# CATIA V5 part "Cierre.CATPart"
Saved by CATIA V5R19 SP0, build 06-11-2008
Part number: Cierre
Material "Plastic": density 1200 kg/m3, Young's modulus 2.2e+09 Pa, Poisson ratio 0.38, thermal expansion 6.84e-05 1/K
Bounding box of the stored display mesh (mm): x -7.75 to 7.75, y -18 to 0, z -6 to 6
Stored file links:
  C:\Users\José Miguel\Documents\Aprendizaxe Catia\Ejercicios_El gran libro de Catia\lote1\73_v5r19\Cierre.CATPart
  D:\TR\libro\ejemplo\terminados\COMPAS\compas.CATProduct
  D:\TR\libro\ejemplo\terminados\COMPAS\MANGO.CATPart
  C:\Users\José Miguel\Documents\Aprendizaxe Catia\Ejercicios_El gran libro de Catia\lote1\73_v5r19\Empunadura.CATPart
  D:\F&IC\ADMIN\MARKETING\logo\catia\CATIA5.es\Sello.CATPart
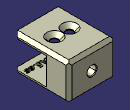
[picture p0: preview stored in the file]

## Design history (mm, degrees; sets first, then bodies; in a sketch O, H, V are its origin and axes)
Body1 "PartBody" (main body)
  Sketch1 on xy-plane, origin (0, 0, 0), H (1, 0, 0), V (0, 1, 0)
    point P1 (-7.75, 0)
    line L1 (-7.75, 0) -> (7.75, 0)
    line L2 (7.75, 0) -> (7.75, -18)
    line L3 (7.75, -18) -> (-7.75, -18)
    line L4 (-7.75, -18) -> (-7.75, 0)
    length L1 = 15.5
    length L2 = 18
    coincidence: P1 H
    horizontal: L1 H, L3 H
    vertical: L2 V, L4 V
    symmetry: L2 L4 V
  Pad1: profile Sketch1, direction (0, 0, 1), length 6, mirrored extent
  Chamfer1: length 1, angle 45, on face of Pad1 from Sketch1.L1; edge [face of Pad1 from Sketch1.L2 | end face of Pad1]; edge [start face of Pad1 | face of Pad1 from Sketch1.L2]; edge [face of Pad1 from Sketch1.L4 | end face of Pad1]; edge [start face of Pad1 | face of Pad1 from Sketch1.L4]; edge [face of Pad1 from Sketch1.L2 | face of Pad1 from Sketch1.L3]; edge [face of Pad1 from Sketch1.L3 | face of Pad1 from Sketch1.L4]
  Sketch2 on yz-plane, origin (0, 0, 0), H (0, 1, 0), V (0, 0, 1)
    projected line E1 (-18, 6) -> (-18, -6) from face of Pad1 from Sketch1.L3
    projected line E2 (-18, 4.5) -> (-18, -4.5) from face of Pad1 from Sketch1.L3
    projected line E3 (-1, 6) -> (-18, 6) from end face of Pad1
    projected line E4 (-18, -6) -> (-1, -6) from start face of Pad1
    line L1 (-7.5, 4.5) -> (-7.5, -4.5)
    line L2 (-7.5, 4.5) -> (-18, 4.5)
    line L3 (-7.5, -4.5) -> (-18, -4.5)
    distance L1 E1 = 10.5
    distance L2 E3 = 1.5
    vertical: L1 V
    horizontal: L2 H, L3 H
    symmetry: L2 L3 H
  Pocket1: profile Sketch2, direction (-1, 0, 0), through (limit type 3), opposite side through (limit type 3)
  Sketch3 on face of Pocket1 from Sketch2.L1, origin (0, -7.5, 0), H (1, 0, 0), V (0, 0, 1)
    line L1 (6.25, 3.5) -> (6.25, -3.5)
    line L2 (5.25, -4.5) -> (-5.25, -4.5)
    line L3 (-6.25, -3.5) -> (-6.25, 3.5)
    line L4 (-5.25, 4.5) -> (5.25, 4.5)
    reference projected line E1 (-7.75, 4.5) -> (7.75, 4.5) from face of Pocket1 from Sketch2.L2
    reference projected line E2 (7.75, 4.5) -> (7.75, -4.5) from edge [face of Pocket1 from Sketch2.L1 | face of Pad1 from Sketch1.L2]
    arc A1 centre (5.25, 3.5) radius 1 from (5.25, 4.5) to (6.25, 3.5) cw
    construction line L5 (5.25, 4.5) -> (6.25, 4.5)
    construction line L6 (6.25, 4.5) -> (6.25, 3.5)
    arc A2 centre (-5.25, 3.5) radius 1 from (-5.25, 4.5) to (-6.25, 3.5) ccw
    construction line L7 (-6.25, 4.5) -> (-5.25, 4.5)
    construction line L8 (-6.25, 3.5) -> (-6.25, 4.5)
    arc A3 centre (-5.25, -3.5) radius 1 from (-6.25, -3.5) to (-5.25, -4.5) ccw
    construction line L9 (-6.25, -4.5) -> (-6.25, -3.5)
    construction line L10 (-5.25, -4.5) -> (-6.25, -4.5)
    arc A4 centre (5.25, -3.5) radius 1 from (5.25, -4.5) to (6.25, -3.5) ccw
    construction line L11 (6.25, -4.5) -> (5.25, -4.5)
    construction line L12 (6.25, -3.5) -> (6.25, -4.5)
    distance L1 E2 = 1.5
    radius A1 = 1
    radius A2 = 1
    radius A3 = 1
    radius A4 = 1
    vertical: L1 V, L3 V
    horizontal: L2 H, L4 H
    equidistance: L1 L3 O, L2 L4 O
    coincidence: L4 E1, L4 L5, L1 L6, L4 L7, L3 L8, L3 L9, L2 L10, L2 L11, L1 L12
    tangency: A1 L4, A1 L1, A2 L4, A2 L3, A3 L3, A3 L2, A4 L2, A4 L1
  Pocket2: profile Sketch3, direction (0, 1, 0), length 3.5
  Sketch4 on end face of Pad1, origin (2.5, -10, 6), H (1, 0, 0), V (0, 1, 0)
    point P1 (0, 0)
    reference projected point E1 (0, 0) from Sketch6.P2
    coincidence: E1 P1
  Hole1: placed by Sketch4, at (2.5, -10, 6) direction (0, 0, -1), diameter 2.5, through (limit type 6), countersink depth 1.25, countersink angle 90
  UserPattern1: of Hole1, copies 2, at the points of Sketch6
  Sketch5 on face of Pocket2, origin (2.5, -10, -4.5), H (1, 0, 0), V (0, 1, 0)
    point P1 (0, 0)
    reference projected point E1 (0, 0) from Sketch6.P2
    coincidence: E1 P1
  Hole2: placed by Sketch5, at (2.5, -10, -4.5) direction (0, 0, -1), diameter 2.013, through (limit type 6), threaded "M2.5", thread diameter 2.5, thread depth 1.5, pitch 0.45
  Sketch6 on xy-plane, origin (0, 0, 0), H (1, 0, 0), V (0, 1, 0)
    construction line L1 (-2.5, -10) -> (2.5, -10)
    point P1 (-2.5, -10)
    point P2 (2.5, -10)
    length L1 = 5
    distance H L1 = 10
    horizontal: L1 H
    symmetry: P2 P1 V
  UserPattern2: of Hole2, copies 2, at the points of Sketch6
  Sketch7 on zx-plane, origin (0, 0, 0), H (-1, 0, 0), V (0, 0, 1)
    point P1 (0, 0)
    coincidence: P1 O
  Sketch8 on face of Pad1 from Sketch1.L1, origin (0, 0, 0), H (1, 0, 0), V (0, 0, -1)
    point P1 (0, 0)
    reference projected point E1 (0, 0) from Sketch7.P1
    coincidence: E1 P1
  Hole3: placed by Sketch8, at (0, 0, 0) direction (0, -1, 0), diameter 3, through (limit type 6)
  Chamfer2: length 0.2, angle 45, on face of Hole3
  Body2 "PartBody"
    Set1
      Plane1: type Tangent, Support face of Pocket2, RefPoint Point1
      Sketch9 on Plane1, origin (0, -15, -4.5), H (1, 0, 0), V (0, 1, 0)
        line L1 (16.2467, 5.257) -> (11.2194, 5.257)
        point P1 (16.2467, 5.257)
        point P2 (11.2194, 5.257)
        line L2 (11.2194, 5.257) -> (9.6982, 0.1478)
        point P3 (9.6982, 0.1478)
        line L3 (9.6982, 0.1478) -> (11.3081, 0.0251)
        point P4 (11.3081, 0.0251)
        unspec C1
        point P5 (10.967, -1.5711)
        line L4 (10.967, -1.5711) -> (9.0639, -1.7416)
        point P6 (9.0639, -1.7416)
        unspec C2
        point P7 (12.0993, 1.9282)
        line L5 (12.0993, 1.9282) -> (12.5564, 3.4698)
        point P8 (12.5564, 3.4698)
        line L6 (12.5564, 3.4698) -> (15.8783, 3.4698)
        point P9 (15.8783, 3.4698)
        line L7 (15.8783, 3.4698) -> (16.2467, 5.257)
        line L8 (-1.1612, 5.3934) -> (-3.2145, 5.3934)
        point P10 (-1.1612, 5.3934)
        point P11 (-3.2145, 5.3934)
        line L9 (-3.2145, 5.3934) -> (-5.3086, -4.6066)
        point P12 (-5.3086, -4.6066)
        line L10 (-5.3086, -4.6066) -> (-3.2486, -4.6066)
        point P13 (-3.2486, -4.6066)
        line L11 (-3.2486, -4.6066) -> (-1.1612, 5.3934)
        line L12 (-4.4218, 5.3934) -> (-12.3004, 5.3934)
        point P14 (-4.4218, 5.3934)
        point P15 (-12.3004, 5.3934)
        line L13 (-12.3004, 5.3934) -> (-12.6483, 3.7222)
        point P16 (-12.6483, 3.7222)
        line L14 (-12.6483, 3.7222) -> (-9.7151, 3.7222)
        point P17 (-9.7151, 3.7222)
        line L15 (-9.7151, 3.7222) -> (-11.4614, -4.6066)
        point P18 (-11.4614, -4.6066)
        line L16 (-11.4614, -4.6066) -> (-9.4014, -4.6066)
        point P19 (-9.4014, -4.6066)
        line L17 (-9.4014, -4.6066) -> (-7.6619, 3.7222)
        point P20 (-7.6619, 3.7222)
        line L18 (-7.6619, 3.7222) -> (-4.7697, 3.7222)
        point P21 (-4.7697, 3.7222)
        line L19 (-4.7697, 3.7222) -> (-4.4218, 5.3934)
        line L20 (-13.0683, -4.6066) -> (-14.6917, 5.3934)
        point P22 (-13.0683, -4.6066)
        point P23 (-14.6917, 5.3934)
        line L21 (-14.6917, 5.3934) -> (-16.9769, 5.3934)
        point P24 (-16.9769, 5.3934)
        line L22 (-16.9769, 5.3934) -> (-22.6317, -4.6066)
        point P25 (-22.6317, -4.6066)
        line L23 (-22.6317, -4.6066) -> (-20.5171, -4.6066)
        point P26 (-20.5171, -4.6066)
        line L24 (-20.5171, -4.6066) -> (-19.3166, -2.3965)
        point P27 (-19.3166, -2.3965)
        line L25 (-19.3166, -2.3965) -> (-15.3534, -2.3965)
        point P28 (-15.3534, -2.3965)
        line L26 (-15.3534, -2.3965) -> (-15.0192, -4.6066)
        point P29 (-15.0192, -4.6066)
        line L27 (-15.0192, -4.6066) -> (-13.0683, -4.6066)
        line L28 (-15.6058, -0.7321) -> (-16.1856, 3.2925)
        point P30 (-15.6058, -0.7321)
        point P31 (-16.1856, 3.2925)
        line L29 (-16.1856, 3.2925) -> (-18.6003, -0.7321)
        point P32 (-18.6003, -0.7321)
        line L30 (-18.6003, -0.7321) -> (-15.6058, -0.7321)
        unspec C3
        point P33 (-24.7463, -1.0049)
        point P34 (-24.1187, 2.1328)
        line L31 (-24.1187, 2.1328) -> (-22.1474, 2.3238)
        point P35 (-22.1474, 2.3238)
        unspec C4
        point P36 (-22.6726, -1.3187)
        line L32 (-22.6726, -1.3187) -> (-24.7463, -1.0049)
        unspec C5
        point P37 (27.4404, -1.5916)
        point P38 (27.2153, -2.6625)
        line L33 (27.2153, -2.6625) -> (25.4622, -2.3692)
        point P39 (25.4622, -2.3692)
        unspec C6
        point P40 (22.5291, -1.5916)
        line L34 (22.5291, -1.5916) -> (27.4404, -1.5916)
        line L35 (22.7269, -0.3979) -> (25.7896, -0.3979)
        point P41 (22.7269, -0.3979)
        point P42 (25.7896, -0.3979)
        unspec C7
        line L36 (7.495, -4.6066) -> (5.8715, 5.3934)
        point P43 (7.495, -4.6066)
        point P44 (5.8715, 5.3934)
        line L37 (5.8715, 5.3934) -> (3.5864, 5.3934)
        point P45 (3.5864, 5.3934)
        line L38 (3.5864, 5.3934) -> (-2.0685, -4.6066)
        point P46 (-2.0685, -4.6066)
        line L39 (-2.0685, -4.6066) -> (0.0461, -4.6066)
        point P47 (0.0461, -4.6066)
        line L40 (0.0461, -4.6066) -> (1.2467, -2.3965)
        point P48 (1.2467, -2.3965)
        line L41 (1.2467, -2.3965) -> (5.2098, -2.3965)
        point P49 (5.2098, -2.3965)
        line L42 (5.2098, -2.3965) -> (5.5441, -4.6066)
        point P50 (5.5441, -4.6066)
        line L43 (5.5441, -4.6066) -> (7.495, -4.6066)
        line L44 (4.9574, -0.7321) -> (4.3776, 3.2925)
        point P51 (4.9574, -0.7321)
        point P52 (4.3776, 3.2925)
        line L45 (4.3776, 3.2925) -> (1.9629, -0.7321)
        point P53 (1.9629, -0.7321)
        line L46 (1.9629, -0.7321) -> (4.9574, -0.7321)
        unspec C8
        point P54 (35.3053, 0.9118)
        point P55 (29.8006, -2.2805)
        line L47 (29.8006, -2.2805) -> (27.9042, -2.5807)
        point P56 (27.9042, -2.5807)
        unspec C9
        point P57 (33.4977, 0.5981)
        line L48 (33.4977, 0.5981) -> (35.3053, 0.9118)
        circle A1 centre (17.6957, -3.6338) radius 1.0362
        fix: P1, P2, P3, P4, P5, P6, P7, P8, P9, P10, P11, P12, P13, P14, P15, P16, P17, P18, P19, P20, P21, P22, P23, P24, P25, P26, P27, P28, P29, P30, P31, P32, P33, P34, P35, P36, P37, P38, P39, P40, P41, P42, P43, P44, P45, P46, P47, P48, P49, P50, P51, P52, P53, P54, P55, P56, P57, L1, L2, L3, C1, L4, C2, L5, L6, L7, L8, L9, L10, L11, L12, L13, L14, L15, L16, L17, L18, L19, L20, L21, L22, L23, L24, L25, L26, L27, L28, L29, L30, C3, L31, C4, L32, C5, L33, C6, L34, L35, C7, L36, L37, L38, L39, L40, L41, L42, L43, L44, L45, L46, C8, L47, C9, L48, A1
      Offset1: Offset face of Pocket2, Length 0.05
      Scaling1: ToTransfor Sketch9, Reference Point1, Ratio 0.2
    Pad2: profile Scaling1, up to face of Pocket2, opposite side up to Offset1
    Set2
      Point1: type OnPlane, Support face of Pocket2, H 0, V -15, Direction (1, 0, 0)
  Add1: tool Body2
